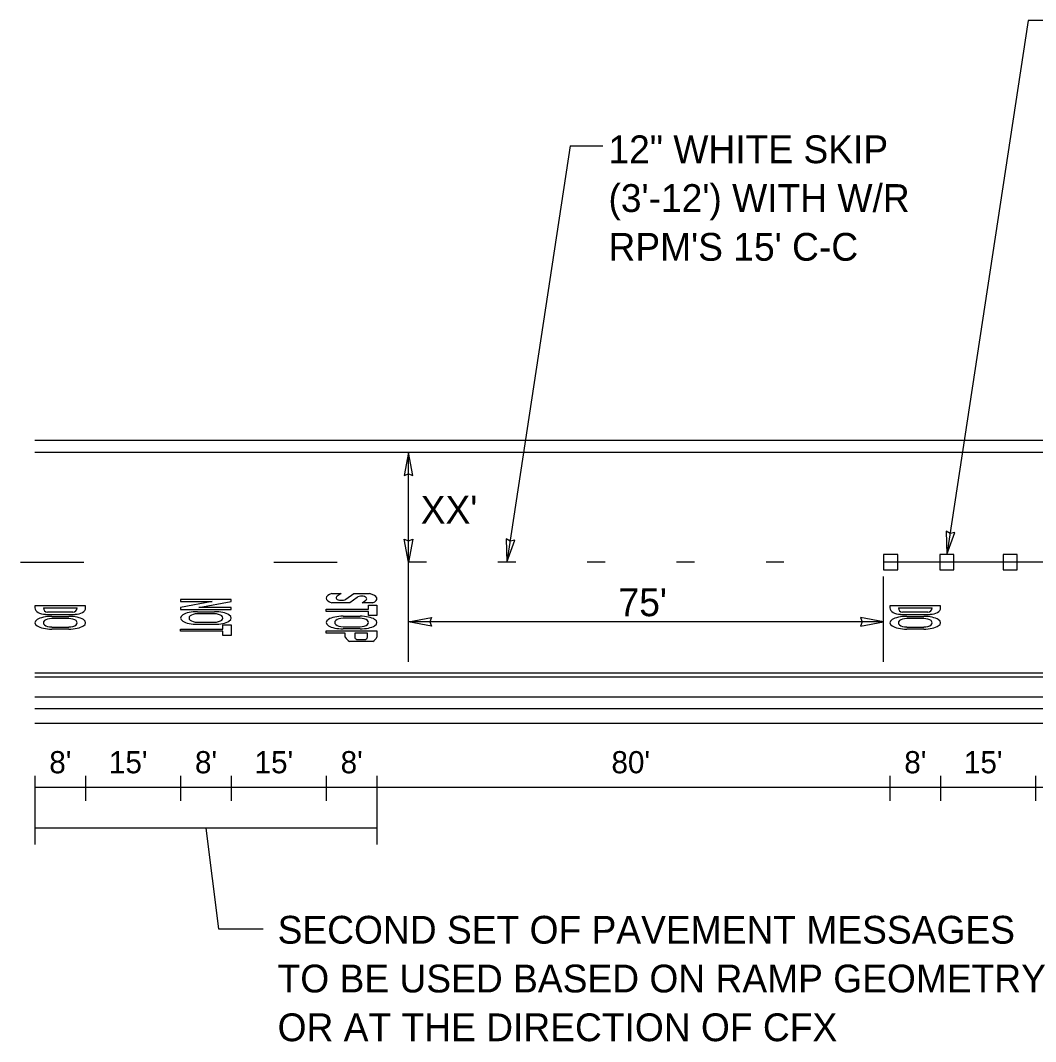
# Model space of a CAD drawing. Extents: x 583689 to 590775, y 1496016 to 1497365.
# Drawn here: x 587322.5 to 587578.1, y 1496182.9 to 1496440 of the extents above; entities that cross this region are included whole.
import ezdxf

# ---------------------------------------------------------------- set-up
doc = ezdxf.new("R2010")
doc.units = 0
for name, color, linetype in [('10', 7, 'Continuous'), ('2', 7, 'Continuous'), ('21', 7, 'Continuous'), ('41', 7, 'Continuous'), ('42', 7, 'Continuous'), ('46', 7, 'Continuous'), ('52', 7, 'Continuous'), ('PavtMessage', 7, 'Continuous'), ('PMStripe6W(10-30)', 7, 'Continuous'), ('TextLabel', 7, 'Continuous')]:
    doc.layers.add(name, color=color, linetype=linetype)

msp = doc.modelspace()

# ---------------------------------------------------------------- linework, layer by layer
at = {"layer": '10'}
for p, q in [((587424.74, 1496303.64), (587420.24, 1496303.64)), ((587447.24, 1496303.64), (587442.74, 1496303.64)), ((587469.74, 1496303.64), (587465.24, 1496303.64)), ((587492.24, 1496303.64), (587487.74, 1496303.64)), ((587514.74, 1496303.64), (587510.24, 1496303.64))]:
    msp.add_line(p, q, dxfattribs=at)
at = {"layer": '2'}
for p, q in [((587663.57, 1496331.25), (587326.15, 1496331.25)), ((587635.53, 1496303.64), (587539.85, 1496303.64)), ((587326.15, 1496274.75), (587663.58, 1496274.75)), ((587387.69, 1496275.75), (587663.57, 1496275.75))]:
    msp.add_line(p, q, dxfattribs=at)
for points in [[(587539.85, 1496301.74), (587543.4, 1496301.74), (587543.4, 1496305.54), (587539.85, 1496305.54)], [(587554.02, 1496301.74), (587557.57, 1496301.74), (587557.57, 1496305.54), (587554.02, 1496305.54)], [(587569.96, 1496301.74), (587573.52, 1496301.74), (587573.52, 1496305.54), (587569.97, 1496305.54)]]:
    msp.add_lwpolyline(points, close=True, dxfattribs=at)
at = {"layer": '21'}
for p, q in [((587576.23, 1496440.04), (587555.8, 1496305.54)), ((587583.82, 1496440.04), (587576.23, 1496440.04)), ((587460.91, 1496408.42), (587444.99, 1496303.64)), ((587460.91, 1496408.42), (587469.14, 1496408.42)), ((587420.24, 1496278.52), (587420.24, 1496331.25)), ((587539.85, 1496278.52), (587539.85, 1496300.03)), ((587539.85, 1496288.57), (587420.24, 1496288.57)), ((587326.15, 1496249.83), (587326.15, 1496232.5)), ((587338.9, 1496249.83), (587338.9, 1496243.54)), ((587362.83, 1496249.83), (587362.83, 1496243.54)), ((587375.58, 1496249.83), (587375.58, 1496243.54)), ((587399.51, 1496249.83), (587399.51, 1496243.54)), ((587412.26, 1496249.83), (587412.26, 1496232.5)), ((587541.44, 1496249.83), (587541.44, 1496243.54)), ((587554.2, 1496249.83), (587554.2, 1496243.54)), ((587578.12, 1496249.83), (587578.12, 1496243.54)), ((587412.26, 1496246.88), (587326.15, 1496246.88)), ((587541.44, 1496246.88), (587412.26, 1496246.88)), ((587635.53, 1496246.88), (587541.44, 1496246.88)), ((587412.26, 1496236.69), (587326.15, 1496236.69)), ((587369.21, 1496236.69), (587372.4, 1496211.31)), ((587372.4, 1496211.31), (587383.61, 1496211.31))]:
    msp.add_line(p, q, dxfattribs=at)
at = {"layer": '41'}
msp.add_line((587326.15, 1496275.75), (587663.57, 1496275.75), dxfattribs=at)
at = {"layer": '42'}
for p, q in [((587663.57, 1496334.25), (587326.15, 1496334.25)), ((587326.15, 1496269.75), (587663.57, 1496269.75)), ((587663.57, 1496263), (587326.15, 1496263))]:
    msp.add_line(p, q, dxfattribs=at)
at = {"layer": '46'}
msp.add_line((587326.15, 1496266.75), (587663.57, 1496266.75), dxfattribs=at)
at = {"layer": '52'}
for p, q in [((587420.24, 1496331.25), (587419.12, 1496325.45)), ((587421.32, 1496325.45), (587420.24, 1496331.25)), ((587419.12, 1496325.45), (587420.24, 1496325.89)), ((587420.24, 1496325.89), (587421.32, 1496325.45)), ((587420.24, 1496303.64), (587419.12, 1496309.44)), ((587419.12, 1496309.44), (587420.24, 1496309)), ((587420.24, 1496309), (587421.32, 1496309.44)), ((587421.32, 1496309.44), (587420.24, 1496303.64)), ((587445.79, 1496308.94), (587444.79, 1496309.53)), ((587444.79, 1496309.53), (587444.99, 1496303.64)), ((587556.6, 1496310.84), (587555.6, 1496311.43)), ((587555.6, 1496311.43), (587555.8, 1496305.54)), ((587555.8, 1496305.54), (587557.77, 1496311.1)), ((587557.77, 1496311.1), (587556.6, 1496310.84)), ((587444.99, 1496303.64), (587446.97, 1496309.2)), ((587446.97, 1496309.2), (587445.79, 1496308.94)), ((587420.24, 1496288.57), (587426.04, 1496289.69)), ((587426.04, 1496289.69), (587425.6, 1496288.57)), ((587539.85, 1496288.57), (587534.05, 1496289.69)), ((587534.05, 1496289.69), (587534.49, 1496288.57)), ((587426.04, 1496287.49), (587420.24, 1496288.57)), ((587425.6, 1496288.57), (587426.04, 1496287.49)), ((587534.49, 1496288.57), (587534.05, 1496287.49)), ((587534.05, 1496287.49), (587539.85, 1496288.57))]:
    msp.add_line(p, q, dxfattribs=at)
at = {"layer": 'PavtMessage'}
for p, q in [((587375.59, 1496294.22), (587362.83, 1496294.22)), ((587362.83, 1496294.22), (587362.83, 1496293.69)), ((587375.59, 1496293.69), (587375.59, 1496294.22)), ((587400.95, 1496295.74), (587403.27, 1496295.74)), ((587403.27, 1496295.74), (587402.26, 1496295.08)), ((587404.4, 1496294.29), (587406.46, 1496295.74)), ((587407.25, 1496294.77), (587405.41, 1496293.35)), ((587406.46, 1496295.74), (587410.36, 1496295.74)), ((587408.56, 1496293.35), (587409.48, 1496294.05)), ((587338.91, 1496292.62), (587326.15, 1496292.62)), ((587326.15, 1496292.62), (587326.15, 1496292.09)), ((587328.28, 1496292.09), (587336.79, 1496292.09)), ((587338.91, 1496292.09), (587338.91, 1496292.62)), ((587362.83, 1496293.69), (587370.8, 1496293.69)), ((587370.8, 1496293.69), (587362.83, 1496292.22)), ((587362.83, 1496292.22), (587362.83, 1496291.69)), ((587362.83, 1496291.69), (587375.59, 1496291.69)), ((587367.45, 1496292.22), (587375.59, 1496293.69)), ((587375.59, 1496292.22), (587367.45, 1496292.22)), ((587375.59, 1496291.69), (587375.59, 1496292.22)), ((587399.51, 1496291.22), (587399.51, 1496291.76)), ((587399.51, 1496291.76), (587410.14, 1496291.76)), ((587405.41, 1496293.35), (587400.95, 1496293.35)), ((587411.18, 1496293.35), (587408.56, 1496293.35)), ((587410.14, 1496292.82), (587412.26, 1496292.82)), ((587410.14, 1496291.76), (587410.14, 1496292.82)), ((587412.26, 1496292.82), (587412.26, 1496290.16)), ((587554.2, 1496292.62), (587541.45, 1496292.62)), ((587541.45, 1496292.62), (587541.45, 1496292.09)), ((587543.57, 1496292.09), (587552.08, 1496292.09)), ((587554.2, 1496292.09), (587554.2, 1496292.62)), ((587328.81, 1496290.49), (587336.25, 1496290.49)), ((587335.72, 1496291.02), (587329.34, 1496291.02)), ((587330.4, 1496289.96), (587334.66, 1496289.96)), ((587334.66, 1496289.43), (587330.4, 1496289.43)), ((587367.08, 1496291.16), (587371.33, 1496291.16)), ((587371.33, 1496290.63), (587367.08, 1496290.63)), ((587410.14, 1496291.22), (587399.51, 1496291.22)), ((587403.76, 1496290.03), (587408.01, 1496290.03)), ((587408.01, 1496289.5), (587403.76, 1496289.5)), ((587410.14, 1496290.16), (587410.14, 1496291.22)), ((587412.26, 1496290.16), (587410.14, 1496290.16)), ((587544.1, 1496290.49), (587551.55, 1496290.49)), ((587551.01, 1496291.02), (587544.64, 1496291.02)), ((587545.7, 1496289.96), (587549.95, 1496289.96)), ((587549.95, 1496289.43), (587545.7, 1496289.43)), ((587330.4, 1496287.3), (587334.66, 1496287.3)), ((587334.66, 1496286.77), (587330.4, 1496286.77)), ((587362.83, 1496286.24), (587362.83, 1496286.77)), ((587362.83, 1496286.77), (587373.46, 1496286.77)), ((587367.08, 1496288.5), (587371.33, 1496288.5)), ((587371.33, 1496287.97), (587367.08, 1496287.97)), ((587373.46, 1496287.83), (587375.59, 1496287.83)), ((587373.46, 1496286.77), (587373.46, 1496287.83)), ((587375.59, 1496287.83), (587375.59, 1496285.17)), ((587399.51, 1496286.31), (587412.26, 1496286.31)), ((587399.51, 1496285.77), (587399.51, 1496286.31)), ((587403.76, 1496287.37), (587408.01, 1496287.37)), ((587408.01, 1496286.84), (587403.76, 1496286.84)), ((587412.26, 1496286.31), (587412.26, 1496284.76)), ((587545.7, 1496287.3), (587549.95, 1496287.3)), ((587549.95, 1496286.77), (587545.7, 1496286.77)), ((587373.46, 1496286.24), (587362.83, 1496286.24)), ((587373.46, 1496285.17), (587373.46, 1496286.24)), ((587375.59, 1496285.17), (587373.46, 1496285.17)), ((587404.29, 1496285.77), (587399.51, 1496285.77)), ((587404.29, 1496284.76), (587404.29, 1496285.77)), ((587409.87, 1496285.77), (587406.68, 1496285.77)), ((587406.68, 1496285.77), (587406.68, 1496284.71)), ((587407.09, 1496284.18), (587409.47, 1496284.18)), ((587409.87, 1496284.71), (587409.87, 1496285.77)), ((587411.2, 1496283.65), (587405.36, 1496283.65))]:
    msp.add_line(p, q, dxfattribs=at)
for centre, start, end in [((587329.34, 1496292.09), 180, 270), ((587335.72, 1496292.09), 270, 0), ((587544.64, 1496292.09), 180, 270), ((587551.02, 1496292.09), 270, 0)]:
    msp.add_arc(centre, 1.06, start, end, dxfattribs=at)
for centre, major_axis, ratio, start_param, end_param in [((587403.76, 1496294.55), (-4.25, 0), 0.375, 5.435123, 7.131247), ((587403.32, 1496294.68), (1.33, 0), 0.5, 2.490106, 5.666015), ((587408.37, 1496294.41), (1.33, 0), 0.5, 5.699287, 8.851109), ((587408.01, 1496294.41), (4.25, 0), 0.375, 5.553458, 7.268296), ((587328.81, 1496292.09), (2.66, 0), 0.6, 3.141593, 4.71335), ((587336.25, 1496292.09), (2.66, 0), 0.6, 4.71335, 6.283185), ((587544.1, 1496292.09), (2.66, 0), 0.6, 3.141593, 4.71335), ((587551.55, 1496292.09), (2.66, 0), 0.6, 4.71335, 6.283185), ((587330.4, 1496288.37), (4.25, 0), 0.375, 1.570796, 4.712389), ((587330.4, 1496288.37), (2.13, 0), 0.5, 1.570796, 4.712389), ((587334.66, 1496288.37), (4.25, 0), 0.375, 4.712389, 7.853982), ((587334.66, 1496288.37), (2.13, 0), 0.5, 4.712389, 7.853982), ((587367.08, 1496289.57), (4.25, 0), 0.375, 1.570796, 4.712389), ((587367.08, 1496289.57), (2.13, 0), 0.5, 1.570796, 4.712389), ((587371.33, 1496289.57), (4.25, 0), 0.375, 4.712389, 7.853982), ((587371.33, 1496289.57), (2.13, 0), 0.5, 4.712389, 7.853982), ((587403.76, 1496288.43), (4.25, 0), 0.375, 1.570796, 4.712389), ((587403.76, 1496288.43), (2.13, 0), 0.5, 1.570796, 4.712389), ((587408.01, 1496288.43), (4.25, 0), 0.375, 4.712389, 7.853982), ((587408.01, 1496288.43), (2.13, 0), 0.5, 4.712389, 7.853982), ((587545.7, 1496288.37), (4.25, 0), 0.375, 1.570796, 4.712389), ((587545.7, 1496288.37), (2.13, 0), 0.5, 1.570796, 4.712389), ((587549.95, 1496288.37), (4.25, 0), 0.375, 4.712389, 7.853982), ((587549.95, 1496288.37), (2.13, 0), 0.5, 4.712389, 7.853982), ((587408.28, 1496285.77), (4.25, 0), 0.6875, 3.497014, 3.955933), ((587408.28, 1496284.71), (1.59, 0), 0.5, 3.141593, 3.87132), ((587408.28, 1496284.71), (1.59, 0), 0.5, 5.553458, 6.283185), ((587408.28, 1496285.77), (4.25, 0), 0.6875, 5.468845, 5.927764)]:
    msp.add_ellipse(centre, major_axis=major_axis, ratio=ratio, start_param=start_param, end_param=end_param, dxfattribs=at)
at = {"layer": 'PMStripe6W(10-30)'}
for p, q in [((587322.49, 1496303.64), (587338.44, 1496303.64)), ((587386.28, 1496303.64), (587402.23, 1496303.64))]:
    msp.add_line(p, q, dxfattribs=at)

# ---------------------------------------------------------------- texts
at = {"layer": '21'}
for s, p in [('12" WHITE SKIP', (587470.57, 1496404.09)), ("(3'-12') WITH W/R", (587470.57, 1496391.81)), ("RPM'S 15' C-C", (587470.57, 1496379.53)), ('SECOND SET OF PAVEMENT MESSAGES', (587387.25, 1496207.57)), ('TO BE USED BASED ON RAMP GEOMETRY', (587387.25, 1496195.29)), ('OR AT THE DIRECTION OF CFX', (587387.25, 1496183.01))]:
    msp.add_text(s, height=7, dxfattribs=at).set_placement(p)
for s, p in [("XX'", (587423.3, 1496313.3)), ("75'", (587473.12, 1496290))]:
    msp.add_text(s, height=7, rotation=0.2102, dxfattribs=at).set_placement(p)
at = {"layer": 'TextLabel'}
for s, p in [("8'", (587329.76, 1496250.47)), ("15'", (587344.77, 1496250.47)), ("8'", (587366.44, 1496250.47)), ("15'", (587381.45, 1496250.47)), ("8'", (587403.12, 1496250.47)), ("80'", (587471.32, 1496250.47)), ("8'", (587545.06, 1496250.47)), ("15'", (587560.07, 1496250.47))]:
    msp.add_text(s, height=5.582, dxfattribs=at).set_placement(p)

doc.saveas('drawing.dxf')
